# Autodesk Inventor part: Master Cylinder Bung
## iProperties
Shininess: 100.0
Angle Display Precision: 2
Document Length Units: 11269
Document Angle Units: 11279
Document Time Units: 11290
Document Mass Units: 11283
Document Length Units Precision: 3
Document Angle Units Precision: 2
Compacted: True
Created: 2001-08
Part Number: Master Cylinder Bung
Document SubType Name: Modeling
Designer: Martin Budgell
Density: 0.0
Volumn: 0.0
Area: 0.0
PropertySet Name: Model Information
Control State: 0
Master: False
Checked Out: False
Author: Martin Budgell
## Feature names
1. Extrusion1
2. Extrusion2
3. Hole1
4. Revolution1
